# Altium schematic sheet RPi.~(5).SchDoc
size A
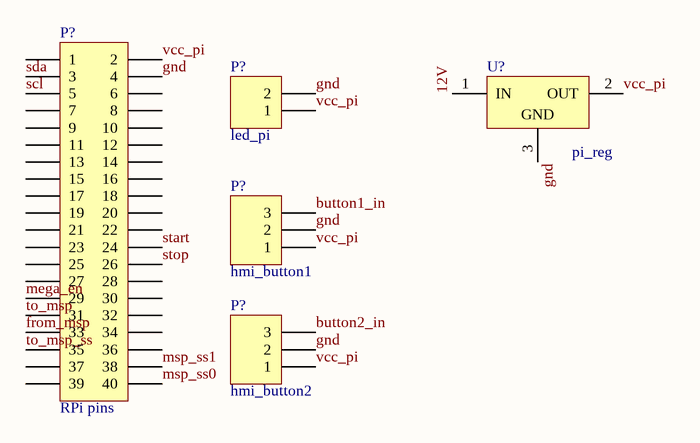
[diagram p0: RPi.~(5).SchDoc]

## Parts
(Parts that share a designator on the sheet are numbered #1, #2 ... from top to bottom, then left to right.)
P?#1  RPi pins  [HDR2X20]
P?#2  led_pi  [HDR1X2H]
P?#3  hmi_button1  [HDR1X3H]
P?#4  hmi_button2  [HDR1X3H]
U?  pi_reg  [TO220ABN]

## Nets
12V: U?.1(IN)
button1_in: P?#3.3
button2_in: P?#4.3
from_msp: P?#1.33
gnd: P?#1.4 P?#2.2 P?#3.2 P?#4.2 U?.3(GND)
mega_en: P?#1.29
msp_ss0: P?#1.40
msp_ss1: P?#1.38
scl: P?#1.5
sda: P?#1.3
start: P?#1.24
stop: P?#1.26
to_msp: P?#1.31
to_msp_ss: P?#1.35
vcc_pi: P?#1.2 P?#2.1 P?#3.1 P?#4.1 U?.2(OUT)

Not connected (* = marked no-connect by the designer): P?#1 1 6 7 8 9 10 11 12 13 14 15 16 17 18 19 20 21 22 23 25 27 28 30 32 34 36 37 39

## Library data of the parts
P?#1 = Header 20X2: Header, 20-Pin, Dual row
P?#2 = Header 2H: Header, 2-Pin, Right Angle
P?#3 P?#4 = Header 3H: Header, 3-Pin, Right Angle
U? = L7805CV: Positive Voltage Regulator; Note: Tab is connected to pin 3 (GND).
